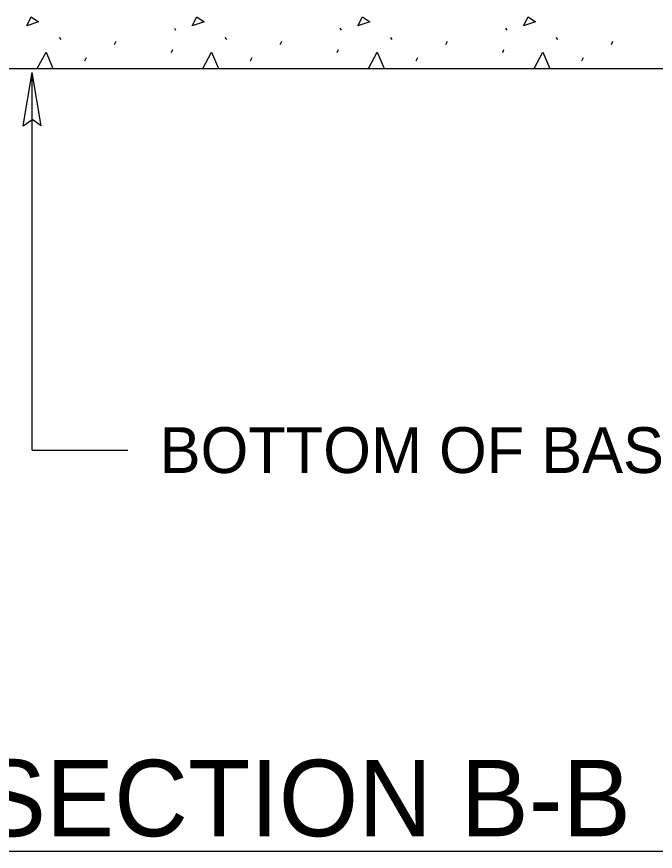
# Model space of a CAD drawing. Extents: x 4.74 to 11.91, y -5.26 to 4.54.
# Drawn here: x 6.963 to 7.798, y -2.334 to -1.242 of the extents above; entities that cross this region are included whole.
import ezdxf

# ---------------------------------------------------------------- set-up
doc = ezdxf.new("R2010")
doc.units = 0
for name, color, linetype in [('DETL-DIMS', 7, 'Continuous'), ('DETL-LINE', 7, 'Continuous'), ('DETL-NOTE', 7, 'Continuous'), ('DETL-PATT', 7, 'Continuous'), ('DETL-TITL', 7, 'Continuous')]:
    doc.layers.add(name, color=color, linetype=linetype)

msp = doc.modelspace()

# ---------------------------------------------------------------- linework, layer by layer
at = {"layer": 'DETL-DIMS'}
for p, q in [((6.9712, -1.3849), (6.9829, -1.3149)), ((6.9829, -1.8091), (6.9829, -1.3149)), ((6.9946, -1.3849), (6.9829, -1.3149)), ((6.9712, -1.3849), (6.9829, -1.3762)), ((6.9946, -1.3849), (6.9829, -1.3762)), ((6.9829, -1.8091), (7.0246, -1.8091)), ((7.0246, -1.8091), (7.0663, -1.8091)), ((7.0663, -1.8091), (7.1079, -1.8091))]:
    msp.add_line(p, q, dxfattribs=at)
at = {"layer": 'DETL-LINE'}
msp.add_line((6.0977, -1.3098), (8.612, -1.3098), dxfattribs=at)
at = {"layer": 'DETL-PATT'}
for p, q in [((7.1689, -1.2569), (7.1705, -1.2596)), ((7.3855, -1.2569), (7.3871, -1.2596)), ((7.6022, -1.2569), (7.6038, -1.2596)), ((7.018, -1.2692), (7.0202, -1.2719)), ((7.0905, -1.2784), (7.0926, -1.2741)), ((7.2347, -1.2692), (7.2368, -1.2719)), ((7.3072, -1.2784), (7.3093, -1.2741)), ((7.4514, -1.2692), (7.4535, -1.2719)), ((7.5238, -1.2784), (7.526, -1.2741)), ((7.668, -1.2692), (7.6702, -1.2719)), ((7.7405, -1.2784), (7.7426, -1.2741)), ((7.1651, -1.2889), (7.1667, -1.2847)), ((7.3818, -1.2889), (7.3834, -1.2847)), ((7.5984, -1.2889), (7.6, -1.2847)), ((7.0518, -1.2997), (7.054, -1.2954)), ((7.2685, -1.2997), (7.2707, -1.2954)), ((7.4852, -1.2997), (7.4873, -1.2954)), ((7.7018, -1.2997), (7.704, -1.2954))]:
    msp.add_line(p, q, dxfattribs=at)
for points in [[(6.9756, -1.2537), (6.9815, -1.2419), (6.9912, -1.2488), (6.9756, -1.2537)], [(7.1923, -1.2537), (7.1982, -1.2419), (7.2079, -1.2488), (7.1923, -1.2537)], [(7.409, -1.2537), (7.4149, -1.2419), (7.4245, -1.2488), (7.409, -1.2537)], [(7.6256, -1.2537), (7.6315, -1.2419), (7.6412, -1.2488), (7.6256, -1.2537)], [(6.9894, -1.3098), (7.0009, -1.2884), (7.01, -1.3098)], [(7.2061, -1.3098), (7.2175, -1.2884), (7.2267, -1.3098)], [(7.4228, -1.3098), (7.4342, -1.2884), (7.4433, -1.3098)], [(7.6394, -1.3098), (7.6509, -1.2884), (7.66, -1.3098)]]:
    msp.add_lwpolyline(points, dxfattribs=at)
at = {"layer": 'DETL-TITL'}
msp.add_line((6.8885, -2.3342), (7.9378, -2.3342), dxfattribs=at)

# ---------------------------------------------------------------- texts
at = {"layer": 'DETL-NOTE'}
msp.add_text('BOTTOM OF BASE UNIT', height=0.06, dxfattribs=at).set_placement((7.1496, -1.8391))
at = {"layer": 'DETL-TITL'}
msp.add_text('SECTION B-B', height=0.1, dxfattribs=at).set_placement((6.9116, -2.3145))

doc.saveas('drawing.dxf')
